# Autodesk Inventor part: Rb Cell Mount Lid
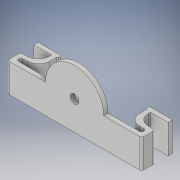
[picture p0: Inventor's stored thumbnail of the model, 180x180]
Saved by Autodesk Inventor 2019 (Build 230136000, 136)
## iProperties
Created: 2019-02
Part Number: Rb Cell Mount Lid
Material: Generic
Document SubType Name: Modeling
Designer: Rydberg
Density: 1 g/cm^3
Appearance: Default
Author: Rydberg
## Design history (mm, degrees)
sketch "Sketch1"
  geometry: L1 (0, 0)-(41, 0); L2 (41, 0)-(41, -13.2); L3 (41, -13.2)-(0, -13.2); L4 (0, -13.2)-(0, 0); C1 r 13.2 at (20.5, -13.2)
  constraints: 8 end point, 2 parallel, 1 centre point, 1 horizontal, 1 midpoint, 1 perpendicular
  dimensions: "d0" = 41 distance of L2.end L3.end; "d1" = 13.2 distance of L1.end L2.end; "d2" = 26.4 diameter of C1
extrude "Extrusion1" new body sketch "Sketch1" distance "d3" = 2; taper "d4" = 0 deg
sketch "Sketch2"
  geometry: L1 (41, 0)-(0, 0) reference; L2 (0, 0)-(-2, 0); L3 (-2, 0)-(-2, -13.2); L4 (-2, -13.2)-(0, -13.2); L5 (0, -13.2)-(0, 0); L6 (41, 0)-(43, 0); L7 (43, 0)-(43, -13.2); L8 (43, -13.2)-(41, -13.2); L9 (41, -13.2)-(41, 0)
  constraints: 16 end point, 4 parallel, 2 horizontal, 2 perpendicular, 1 point on line
  dimensions: "d5" = 2 distance of L4.end L3.end; "d6" = 2 distance of L8.end L7.end
extrude "Extrusion2" join sketch "Sketch2" distance "d7" = 12.5; taper "d8" = 0 deg
sketch "Sketch3"
  geometry: 1 further point
sketch "Sketch4"
  geometry: L1 (-2, -2)-(-2, 10.5) reference; L2 (-2, 10.5)-(-2, 12); L3 (-2, 12)-(1, 12); L4 (1, 12)-(0.3, 10.5); L5 (0, 0)-(0, 10.5) reference; L6 (0.3, 10.5)-(0, 10.5); L7 (43, 10.5)-(41, 10.5) reference; L8 (43, 10.5)-(43, 12); L9 (43, 12)-(40, 12); L10 (-2, 10.5)-(0, 10.5); L11 (43, 10.5)-(40.7, 10.5); L12 (40.7, 10.5)-(40, 12)
  constraints: 18 end point, 3 perpendicular, 2 vertical, 1 parallel, 1 point on line
  dimensions: "d9" = 1.5 distance of L1.end L2.end; "d10" = 3 distance of L2.end L3.end; "d11" = 0.3 distance of L4.end L5.end; "d12" = 1.5 distance of L7.start L8.end; "d13" = 3 distance of L8.end L9.end; "d14" = 2.3 distance of L7.start L11.end
extrude "Extrusion3" join sketch "Sketch4" stored distance "d15" = 8; taper "d16" = 0 deg
fillet "Fillet1" dims "d17" = 0.5
fillet "Fillet2" dims "d18" = 0.5
sketch "Sketch5"
  geometry: L1 (-1, 0)-(42, 0); L2 (42, 0)-(42, 1.316); L3 (42, 1.316)-(-1, 1.316); L4 (-1, 1.316)-(-1, 0); L5 (0, 0)-(0, 10.5) reference; L6 (41, 0)-(41, 10.5) reference
  constraints: 8 end point, 2 parallel, 1 horizontal, 1 perpendicular
  dimensions: "d19" = 1 distance between parallel lines of L5 L4; "d20" = 1 distance between parallel lines of L6 L2
extrude "Extrusion4" cut sketch "Sketch5" extent not by distance; stored distance "d21" = 8; taper "d22" = 0 deg
sketch "Sketch6"
  geometry: C1 r 2 at (20.5, -13.2); A1 r 13.2 centre (20.5, -13.2) between (7.3, -13.2) and (33.7, -13.2) reference; 1 further point
  constraints: 1 centre point, 1 coincident
  dimensions: "d23" = 4 diameter of C1
extrude "Extrusion5" cut sketch "Sketch6" distance "d24" = 8; taper "d25" = 0 deg
sketch "Sketch7"
  geometry: L1 (-43, 0)-(-41, 0) reference; L2 (-41, 0)-(-51, 0); L3 (-51, 0)-(-51, -6); L4 (-51, -6)-(-41, -6); L5 (-41, -6)-(-41, 0); L6 (0, 0)-(2, 0) reference; L7 (0, 0)-(10, 0); L8 (10, 0)-(10, -6); L9 (10, -6)-(0, -6); L10 (0, -6)-(0, 0); 1 further point
  constraints: 16 end point, 4 parallel, 2 horizontal, 2 perpendicular
  dimensions: "d26" = 10 distance of L4.end L3.end; "d27" = 6 distance of L3.end L2.end; "d28" = 10 distance of L8.end L9.end; "d29" = 6 distance of L7.end L8.end
extrude "Extrusion6" join sketch "Sketch7" stored distance "d30" = 1.7; taper "d31" = 0 deg
sketch "Sketch8"
  geometry: L1 (-49, 8.5)-(8, 8.5); L2 (8, 8.5)-(8, 10.5); L3 (8, 10.5)-(-49, 10.5); L4 (-49, 10.5)-(-49, 8.5); L5 (-51, 12.5)-(-51, 6.5) reference; L6 (-51, 6.5)-(-43, 6.5) reference; L7 (-51, 12.5)-(-33.7, 12.5) reference; L8 (10, 12.5)-(10, 6.5) reference; 3 further points
  constraints: 8 end point, 2 parallel, 1 horizontal, 1 perpendicular
  dimensions: "d32" = 2 distance between parallel lines of L5 L4; "d33" = 2 distance between parallel lines of L6 L1; "d34" = 2 distance between parallel lines of L7 L3; "d35" = 2 distance between parallel lines of L2 L8
extrude "Extrusion7" cut sketch "Sketch8" extent not by distance; stored distance "d36" = 1.7; taper "d37" = 0 deg
sketch "Sketch9"
  geometry: L1 (-40.785, -1.5)-(-42.5, -1.5) reference; L2 (-41, -1.5)-(-51, -1.5); L3 (-51, -1.5)-(-51, 0.5); L4 (-51, 0.5)-(-41, 0.5); L5 (-41, 0.5)-(-41, -1.5); L6 (0, -1.5)-(10, -1.5); L7 (10, -1.5)-(10, 0.5); L8 (10, 0.5)-(0, 0.5); L9 (0, 0.5)-(0, -1.5); 1 further point
  constraints: 16 end point, 4 parallel, 2 horizontal, 2 perpendicular, 1 point on line
  dimensions: "d38" = 2 distance of L2.end L3.end; "d39" = 2 distance of L7.end L6.end
extrude "Extrusion8" join sketch "Sketch9" stored distance "d40" = 1.7; taper "d41" = 0 deg
fillet "Fillet3" dims "d42" = 1
fillet "Fillet4" dims "d43" = 5
body "Solid1"
